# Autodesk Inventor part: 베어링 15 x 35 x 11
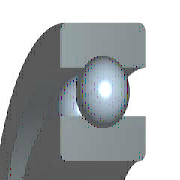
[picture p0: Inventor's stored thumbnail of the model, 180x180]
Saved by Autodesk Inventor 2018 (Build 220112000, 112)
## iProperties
Created: 2012-02
Part Number: 베어링 15 x 35 x 11
Material: 강철, 연강
Description: 깊은 그루브 볼 베어링
Document SubType Name: Modeling
Standard: KS B 2023
Designer: mduedu
Standards Organization: KS
Language: ko-KR
Size Designation: 6202 - 15 x 35 x 11
Categories: <MemberInstance><Categories><Category DisplayName="샤프트 부품" InternalName="7f7aeb1f-a693-4053-b835-cee3144e0d98" Mnemonic="SHFT"><Category DisplayName="베어링" Inter
Density: 1 g/cm^3
Appearance: 밝은 황색
IsCustomPart: 1
Author: mduedu
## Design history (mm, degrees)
sketch "스케치" dims "d0" = 5.2 (= -0.26 x WD + 0.26 x BD)
  geometry: L1 (2.9, 12.5)-(8.1, 12.5); L2 (5.5, 12.5)-(5.5, 9.9); L3 (5.5, 12.5)-(5.5, 15.1); L4 (3.568, 10.76)-(0, 10.76); L5 (0, 7.5)-(11, 7.5); L6 (3.568, 14.24)-(0, 14.24); L7 (0, 17.5)-(11, 17.5); L8 (11, 7.5)-(11, 10.76); L9 (7.432, 10.76)-(11, 10.76); L10 (7.432, 14.24)-(11, 14.24); L11 (11, 17.5)-(11, 14.24); L12 (-1.4, 0)-(8.4, 0) reference; L13 (0, -0.3)-(0, 5.3) reference
  constraints: 22 end point, 4 point on line, 2 collinear, 2 perpendicular, 2 symmetric about line, 1 midpoint, 1 parallel, 14 other
  dimensions: "d9" = 15 diameter of L5 L12 (= WD); "d11" = 35 diameter of L7 L12 (= BD); "d12" = 11 distance between parallel lines of L8 L13 (= KB); "d13" = 21.52 diameter of L9 L12 (= 0.326 x BD + 0.674 x WD)
revolve "본체" stored, may be unused: angle "d6" = 90 deg
revolve "볼" stored, may be unused: angle "d7" = 90 deg
pattern_circular "IDS_ARRAYBALL[SIMPL:T]" dims angle "d3" = 360 deg
body "Solid1"
fillet "모깎기1" dims "d1" = 0.6 (= KRS)
other parameters: "WD" = 15 [user parameter; used in 5 equation terms], "BD" = 35 [user parameter; used in 5 equation terms], "KB" = 11 [user parameter; used in 1 equation term], "KRS" = 0.6 [user parameter; used in 1 equation term], "d4" = 0, "d5" = 0, "d8" = 0, "d14" = 0, "d15" = 0, "BBA" = 0 [user parameter], "BC0" = 3750000 [user parameter], "BC" = 7800000 [user parameter], "BR" = 17.5 (= 0.5 x BD) [user parameter], "WR" = 7.5 (= 0.5 x WD) [user parameter]
